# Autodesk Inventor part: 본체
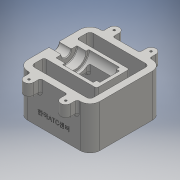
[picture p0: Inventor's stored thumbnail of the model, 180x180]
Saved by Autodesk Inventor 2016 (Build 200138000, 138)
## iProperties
Created: 2018-01
Part Number: 본체
Material: 일반
Document SubType Name: Modeling
Designer: USER
Density: 1 g/cm^3
Appearance: 기본값
Author: USER
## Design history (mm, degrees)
sketch "스케치1"
  geometry: L1 (-55, -55)-(55, -55); L2 (55, -55)-(55, 55); L3 (55, 55)-(-55, 55); L4 (-55, 55)-(-55, -55); L5 (-55, -55)-(55, 55); L6 (55, -55)-(-55, 55); 1 further point
  constraints: 12 end point, 2 midpoint, 2 parallel, 1 horizontal, 1 perpendicular
  dimensions: "d0" = 110 distance of L2.end L3.end; "d1" = 110 distance of L1.end L2.end
extrude "돌출1" new body sketch "스케치1" distance "d2" = 65; taper "d3" = 0 deg
sketch "스케치2"
  geometry: L1 (-55, 55)-(-55, -55) reference; L2 (55, 55)-(-55, 55) reference; L3 (-55, -55)-(55, -55) reference; L4 (-35.5, 65)-(-35.5, 55); L5 (-20.5, 65)-(-20.5, 55); L6 (20.5, 65)-(20.5, 55); L7 (35.5, 65)-(35.5, 55); L8 (20.5, -65)-(20.5, -55); L9 (-20.5, -65)-(-20.5, -55); L10 (-35.5, -65)-(-35.5, -55); L11 (35.5, -65)-(35.5, -55); L12 (-35.5, 55)-(-20.5, 55); L13 (20.5, 55)-(35.5, 55); L14 (35.5, -55)-(20.5, -55); L15 (-20.5, -55)-(-35.5, -55); A1 r 7.5 centre (-28, 65) between (-20.5, 65) and (-35.5, 65); A2 r 7.5 centre (28, 65) between (35.5, 65) and (20.5, 65); A3 r 7.5 centre (28, -65) between (20.5, -65) and (35.5, -65); A4 r 7.5 centre (-28, -65) between (-35.5, -65) and (-20.5, -65); 1 further point
  constraints: 24 end point, 8 point on circle, 8 point on line, 8 tangent, 7 perpendicular, 4 centre point, 3 collinear, 2 horizontal alignment, 2 vertical alignment, 1 horizontal, 1 vertical
  dimensions: "d4" = 15 diameter of A2; "d5" = 15 diameter of A1 (= d4); "d6" = 15 diameter of A4 (= d4); "d7" = 15 diameter of A3 (= d4); "d8" = 27 distance from line of A1.centre L1; "d9" = 56 distance of A2.centre A1.centre; "d10" = 10 distance from line of A1.centre L2; "d11" = 10 distance from line of A4.centre L3
extrude "돌출2" join sketch "스케치2" distance "d12" = 20; taper "d13" = 0 deg
sketch "스케치3"
  geometry: L1 (-45, 45)-(45, 45); L2 (45, 45)-(45, -45); L3 (45, -45)-(-45, -45); L4 (-45, -45)-(-45, -25); L5 (-45, -25)-(35, -25); L6 (35, -25)-(35, 25); L7 (35, 25)-(-45, 25); L8 (-45, 25)-(-45, 45); L9 (20.5, 55)-(-20.5, 55) reference; L10 (-55, 55)-(-55, -55) reference; L11 (55, -55)-(55, 55) reference; L12 (-20.5, -55)-(20.5, -55) reference; 1 further point
  constraints: 16 end point, 7 perpendicular, 1 horizontal, 1 point on line
  dimensions: "d14" = 30 distance between parallel lines of L7 L9; "d15" = 20 distance between parallel lines of L1 L7; "d16" = 10 distance between parallel lines of L8 L10; "d17" = 10 distance between parallel lines of L11 L2; "d18" = 10 distance between parallel lines of L12 L3; "d19" = 20 distance between parallel lines of L3 L5; "d23" = 20 distance between parallel lines of L11 L6
extrude "돌출3" cut sketch "스케치3" stored distance "d21" = 20; taper "d22" = 0 deg
sketch "스케치4"
  geometry: L1 (45, 8.564)-(45, 0); L2 (45, 0)-(-35, 0); L3 (-55, 0)-(55, 0) reference; L4 (45, 8.564)-(-35, 30); L5 (-35, 65)-(-35, 0) reference; L6 (-35, 30)-(-35, 0); L7 (55, 0)-(55, 65) reference; 1 further point
  constraints: 8 end point, 1 collinear, 1 perpendicular, 1 point on line, 1 vertical alignment
  dimensions: "d24" = 30 distance from line of L3 L4.end; "d25" = 105 deg angle of L4 L1; "d26" = 10 distance between parallel lines of L1 L7
extrude "돌출4" cut sketch "스케치4" stored distance "d27" = 55; taper "d28" = 0 deg
sketch "스케치5"
  geometry: L1 (-35, 30)-(45, 8.564) reference; L2 (-20, 31.157)-(55, 11.061); L3 (55, 0)-(55, 65) reference; L4 (55, 11.061)-(55, 29.061); L5 (55, 29.061)-(17, 39.243); L6 (17, 39.243)-(17, 61.157); L7 (17, 61.157)-(-20, 61.157); L8 (-20, 61.157)-(-20, 31.157); 1 further point
  constraints: 12 end point, 2 parallel, 2 perpendicular, 2 point on line
  dimensions: "d29" = 5 distance between parallel lines of L1 L2; "d30" = 18 distance of L2.end L4.end; "d31" = 37 distance of L6.end L7.end; "d32" = 75 deg angle of L5 L3; "d33" = 38 distance between parallel lines of L6 L3; "d34" = 30 distance of L7.end L2.start
extrude "돌출5" cut sketch "스케치5" stored distance "d35" = 30; taper "d36" = 0 deg
sketch "스케치6"
  geometry: L1 (35.5, 65)-(55, 65) reference; L2 (55, 65)-(101.354, 65); L3 (55, 0)-(55, 65) reference; L4 (55, 65)-(55, 57.5); L5 (55, 57.5)-(36, 57.5); L6 (36, 57.5)-(36, 49); L7 (36, 49)-(22, 49); L8 (22, 49)-(22, 45); L9 (35.5, 45)-(20.5, 45) reference; L10 (22, 45)-(-25, 45); L11 (-25, 45)-(-25, 50); L12 (-25, 50)-(-30, 50); L13 (-20.5, 65)-(-35.5, 65) reference; L14 (-30, 50)-(-30, 65); L15 (-30, 65)-(55, 65); 1 further point
  constraints: 22 end point, 6 perpendicular, 2 horizontal, 2 point on line, 1 collinear, 1 vertical
  dimensions: "d37" = 15 diameter of L5 L2; "d38" = 32 diameter of L7 L2; "d39" = 40 diameter of L10 L2; "d40" = 30 diameter of L12 L2; "d41" = 19 distance of L4.end L5.end; "d42" = 14 distance of L6.end L7.end; "d43" = 47 distance of L8.end L10.end; "d44" = 5 distance of L11.end L12.end
revolve "회전1" sketch "스케치6" stored, may be unused: angle "d45" = 90 deg
sketch "스케치7"
  geometry: L1 (0, 0)-(0, 65) reference; L2 (0, 0)-(110, 0) reference; 2 further points
  constraints: 1 other
  dimensions: "d46" = 55 distance from line of point (55, 20) L1; "d47" = 20 distance from line of L2 point (55, 20)
feature "엠보싱1" sketch "스케치7" dims "d0" = 110, "d1" = 110, "d48" = 0.5, "d49" = 0
fillet "모깎기1" dims "d50" = 1
chamfer "모따기1" distance "d51" = 1; stored, may be unused: second distance "d52" = 2, angle "d53" = 45 deg
fillet "모깎기2" dims "d54" = 15
fillet "모깎기3" dims "d55" = 5
fillet "모깎기4" dims "d56" = 3
fillet "모깎기5" dims "d57" = 3
fillet "모깎기6" dims "d58" = 3
fillet "모깎기7" dims "d59" = 3
sketch "스케치8"
  geometry: A1 r 7.5 centre (-28, 65) between (-20.5, 65) and (-35.5, 65) reference; A2 r 7.5 centre (28, 65) between (35.5, 65) and (20.5, 65) reference; A3 r 7.5 centre (28, -65) between (20.5, -65) and (35.5, -65) reference; A4 r 7.5 centre (-28, -65) between (-35.5, -65) and (-20.5, -65) reference; 5 further points
  constraints: 4 coincident
hole "구멍1" sketch "스케치8" at (-28, 65), (28, 65), (28, -65), (-28, -65) diameter "d60" = 3.242; stored, may be unused: countersink angle "d64" = 90 deg, drill point angle "d66" = 118 deg; dims "d61" = 9, "d62" = 4, "d63" = 2, "d65" = 11
fillet "모깎기11" dims "d70" = 3
node "솔리드1"
